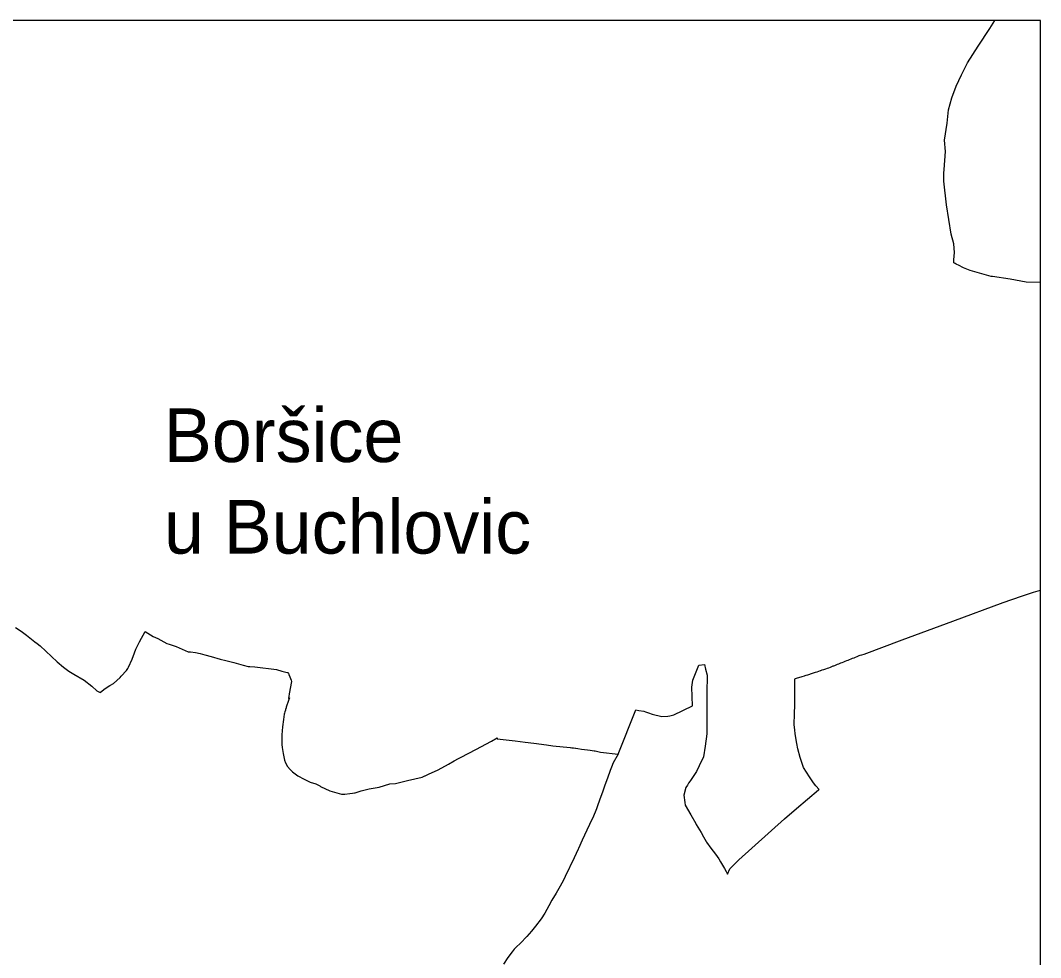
# Model space of a CAD drawing. Extents: x -552716 to -540720, y -1192685 to -1177912.
# Drawn here: x -546493 to -543896, y -1183546 to -1181162 of the extents above; entities that cross this region are included whole.
import ezdxf

# ---------------------------------------------------------------- set-up
doc = ezdxf.new("R2010")
doc.units = 0
doc.layers.add('Vrstva 1', color=7, linetype='Continuous')
doc.layers.add('Vrstva 60', color=7, linetype='Continuous')

msp = doc.modelspace()

# ---------------------------------------------------------------- linework, layer by layer
at = {"layer": 'Vrstva 1'}
for p, q in [((-546504.7, -1182705.9), (-546490.6, -1182715.5)), ((-546490.6, -1182715.5), (-546477.2, -1182725.3)), ((-546477.2, -1182725.3), (-546455.6, -1182742.2)), ((-546189.2, -1182742.6), (-546174.9, -1182716.2)), ((-546174.9, -1182716.2), (-546154.4, -1182729.1)), ((-546154.4, -1182729.1), (-546143, -1182734.3)), ((-546143, -1182734.3), (-546120.1, -1182746.8)), ((-546455.6, -1182742.2), (-546449.7, -1182746.6)), ((-546449.7, -1182746.6), (-546442.5, -1182752.4)), ((-546442.5, -1182752.4), (-546413.2, -1182780)), ((-546202.6, -1182770.3), (-546198.6, -1182761.4)), ((-546198.6, -1182761.4), (-546189.2, -1182742.6)), ((-546120.1, -1182746.8), (-546114.2, -1182748.4)), ((-546114.2, -1182748.4), (-546096.2, -1182754)), ((-546096.2, -1182754), (-546065.9, -1182767.7)), ((-546413.2, -1182780), (-546399.4, -1182793.2)), ((-546217.8, -1182807), (-546208.3, -1182786.7)), ((-546208.3, -1182786.7), (-546202.6, -1182770.3)), ((-546065.9, -1182767.7), (-546059.3, -1182767.9)), ((-546059.3, -1182767.9), (-546046.7, -1182769.2)), ((-546046.7, -1182769.2), (-546035.1, -1182772.4)), ((-546035.1, -1182772.4), (-546023.6, -1182775.5)), ((-546023.6, -1182775.5), (-546007.3, -1182779.9)), ((-546007.3, -1182779.9), (-545983.8, -1182786.2)), ((-545983.8, -1182786.2), (-545969.8, -1182789.8)), ((-546399.4, -1182793.2), (-546382.8, -1182806.7)), ((-546382.8, -1182806.7), (-546369.4, -1182816.8)), ((-546222.5, -1182815.2), (-546219.5, -1182810.1)), ((-546219.5, -1182810.1), (-546217.8, -1182807)), ((-545969.8, -1182789.8), (-545949.7, -1182795.1)), ((-545949.7, -1182795.1), (-545925.6, -1182801.7)), ((-545925.6, -1182801.7), (-545912.9, -1182805.1)), ((-545912.9, -1182805.1), (-545909, -1182805.6)), ((-545909, -1182805.6), (-545896.2, -1182806.4)), ((-545896.2, -1182806.4), (-545840.9, -1182813)), ((-545840.9, -1182813), (-545827.6, -1182816.9)), ((-546369.4, -1182816.8), (-546356.5, -1182825.1)), ((-546356.5, -1182825.1), (-546330.2, -1182840.2)), ((-546330.2, -1182840.2), (-546310.5, -1182854.9)), ((-546256, -1182848.8), (-546238.6, -1182832.8)), ((-546238.6, -1182832.8), (-546236.2, -1182830.2)), ((-546236.2, -1182830.2), (-546222.5, -1182815.2)), ((-545827.6, -1182816.9), (-545813.9, -1182820.1)), ((-545813.9, -1182820.1), (-545811.1, -1182820.6)), ((-545811.1, -1182820.6), (-545810.5, -1182822.2)), ((-545810.5, -1182822.2), (-545809.2, -1182825.5)), ((-545809.2, -1182825.5), (-545806.8, -1182831.4)), ((-545806.8, -1182831.4), (-545803.7, -1182839.6)), ((-545803.7, -1182839.6), (-545802.4, -1182843)), ((-546310.5, -1182854.9), (-546298.3, -1182866.7)), ((-546288.5, -1182870.7), (-546276.8, -1182861)), ((-546276.8, -1182861), (-546264.7, -1182853.9)), ((-546264.7, -1182853.9), (-546256, -1182848.8)), ((-545802.4, -1182843), (-545808.5, -1182874.6)), ((-546298.3, -1182866.7), (-546289.7, -1182871.7)), ((-546289.7, -1182871.7), (-546288.5, -1182870.7)), ((-545810.3, -1182891.7), (-545815.8, -1182908.9)), ((-545810.4, -1182886.7), (-545807.4, -1182885.2)), ((-545810.2, -1182885.4), (-545810.4, -1182886.7)), ((-545807.4, -1182885.2), (-545810.3, -1182891.7)), ((-545809.8, -1182881.8), (-545810.2, -1182885.4)), ((-545809.7, -1182881.1), (-545809.8, -1182881.8)), ((-545808.5, -1182874.8), (-545809.7, -1182881.1)), ((-545808.5, -1182874.6), (-545808.5, -1182874.8)), ((-545818.1, -1182916.1), (-545819.7, -1182920.9)), ((-545818, -1182915.6), (-545818.1, -1182916.1)), ((-545817.9, -1182915.3), (-545818, -1182915.6)), ((-545817.6, -1182914.4), (-545817.9, -1182915.3)), ((-545816.4, -1182910.6), (-545817.6, -1182914.4)), ((-545815.8, -1182908.9), (-545816.4, -1182910.6)), ((-545823.1, -1182939.7), (-545825.3, -1182958.4)), ((-545821.4, -1182926.8), (-545823.1, -1182939.7)), ((-545820.7, -1182924.1), (-545821.4, -1182926.8)), ((-545819.7, -1182920.9), (-545820.7, -1182924.1)), ((-545825.3, -1182958.4), (-545827.3, -1182979)), ((-545827.3, -1182979), (-545827.4, -1183003.3)), ((-545333.5, -1183016.5), (-545293.9, -1182995.4)), ((-545293.9, -1182995.4), (-545279.6, -1182986.4)), ((-545279.6, -1182986.4), (-545278.8, -1182988.8)), ((-545278.8, -1182988.8), (-545233.3, -1182994.7)), ((-545233.3, -1182994.7), (-545207.8, -1182997.7)), ((-545827.4, -1183003.3), (-545826.2, -1183010.9)), ((-545826.2, -1183010.9), (-545823.9, -1183026.7)), ((-545370.5, -1183035.6), (-545333.5, -1183016.5)), ((-545207.8, -1182997.7), (-545185.9, -1183000.4)), ((-545185.9, -1183000.4), (-545153.4, -1183004.7)), ((-545153.4, -1183004.7), (-545137.4, -1183006.8)), ((-545137.4, -1183006.8), (-545093.3, -1183011.2)), ((-545093.3, -1183011.2), (-545092.8, -1183011.3)), ((-545092.8, -1183011.3), (-545089.5, -1183011.7)), ((-545089.5, -1183011.7), (-545084.8, -1183012.4)), ((-545084.8, -1183012.4), (-545080, -1183013)), ((-545080, -1183013), (-545079.8, -1183013)), ((-545079.8, -1183013), (-545079, -1183013.1)), ((-545079, -1183013.1), (-545073.6, -1183013.9)), ((-545073.6, -1183013.9), (-545064.4, -1183015.2)), ((-545064.4, -1183015.2), (-545056.8, -1183016.2)), ((-545056.8, -1183016.2), (-545049, -1183017.4)), ((-545049, -1183017.4), (-545042.8, -1183018.2)), ((-545042.8, -1183018.2), (-545032.4, -1183019.7)), ((-545032.4, -1183019.7), (-545029.5, -1183020.1)), ((-545029.5, -1183020.1), (-545015.8, -1183023)), ((-545823.9, -1183026.7), (-545820.4, -1183043.7)), ((-545820.4, -1183043.7), (-545817.6, -1183050.4)), ((-545402.9, -1183054), (-545388.8, -1183045.3)), ((-545388.8, -1183045.3), (-545377.6, -1183039.2)), ((-545377.6, -1183039.2), (-545370.5, -1183035.6)), ((-545015.8, -1183023), (-544971.2, -1183027.9)), ((-544971.2, -1183027.9), (-544983.9, -1183050.4)), ((-545817.6, -1183050.4), (-545812.9, -1183059.4)), ((-545812.9, -1183059.4), (-545805.9, -1183067.4)), ((-545805.9, -1183067.4), (-545805.8, -1183067.5)), ((-545805.8, -1183067.5), (-545800.4, -1183073.5)), ((-545800.4, -1183073.5), (-545786.6, -1183083.1)), ((-545453.7, -1183079), (-545429.5, -1183067.7)), ((-545429.5, -1183067.7), (-545402.9, -1183054)), ((-544991.2, -1183069.6), (-544998.3, -1183088.9)), ((-544988.2, -1183061.7), (-544991.2, -1183069.6)), ((-544983.9, -1183050.4), (-544988.2, -1183061.7)), ((-545786.6, -1183083.1), (-545770.7, -1183092)), ((-545770.7, -1183092), (-545755.1, -1183099.5)), ((-545755.1, -1183099.5), (-545740.6, -1183103.7)), ((-545538.1, -1183102.6), (-545507.2, -1183094.9)), ((-545507.2, -1183094.9), (-545470.1, -1183086.6)), ((-545470.1, -1183086.6), (-545463.4, -1183083.4)), ((-545463.4, -1183083.4), (-545462.8, -1183083.2)), ((-545462.8, -1183083.2), (-545454.1, -1183079.1)), ((-545454.1, -1183079.1), (-545453.7, -1183079)), ((-544998.3, -1183088.9), (-545004.9, -1183107.1)), ((-545740.6, -1183103.7), (-545732.3, -1183108.3)), ((-545732.3, -1183108.3), (-545730.6, -1183108.7)), ((-545730.6, -1183108.7), (-545728.6, -1183110.1)), ((-545728.6, -1183110.1), (-545705.2, -1183121.6)), ((-545705.2, -1183121.6), (-545675.1, -1183129.8)), ((-545640.6, -1183126.8), (-545625.6, -1183121.9)), ((-545625.6, -1183121.9), (-545604.6, -1183116.8)), ((-545604.6, -1183116.8), (-545579.8, -1183112.1)), ((-545579.8, -1183112.1), (-545552.5, -1183103.4)), ((-545552.5, -1183103.4), (-545538.1, -1183102.6)), ((-545011.2, -1183124.6), (-545017.7, -1183142.5)), ((-545004.9, -1183107.1), (-545011.2, -1183124.6)), ((-545675.1, -1183129.8), (-545666.6, -1183130.1)), ((-545666.6, -1183130.1), (-545654, -1183128.4)), ((-545654, -1183128.4), (-545647.5, -1183127.6)), ((-545647.5, -1183127.6), (-545642.4, -1183127)), ((-545642.4, -1183127), (-545641.5, -1183126.9)), ((-545641.5, -1183126.9), (-545640.6, -1183126.8)), ((-545017.7, -1183142.5), (-545024.8, -1183162.2)), ((-545027.9, -1183171.3), (-545033.9, -1183186.2)), ((-545026.5, -1183167.2), (-545027.9, -1183171.3)), ((-545025.5, -1183164.4), (-545026.5, -1183167.2)), ((-545024.8, -1183162.2), (-545025.5, -1183164.4)), ((-545033.9, -1183186.2), (-545043.9, -1183207.4)), ((-545050.6, -1183221.6), (-545062.7, -1183246.6)), ((-545043.9, -1183207.4), (-545050.6, -1183221.6)), ((-545062.7, -1183246.6), (-545072.4, -1183268.6)), ((-545073, -1183269.7), (-545083.1, -1183292.1)), ((-545072.4, -1183268.6), (-545073, -1183269.7)), ((-545083.1, -1183292.2), (-545106, -1183339.5)), ((-545083.1, -1183292.1), (-545083.1, -1183292.2)), ((-545110.4, -1183348.7), (-545119.1, -1183364.1)), ((-545106, -1183339.5), (-545110.4, -1183348.7)), ((-545129, -1183382.2), (-545139.8, -1183400)), ((-545119.1, -1183364.1), (-545129, -1183382.2)), ((-545139.8, -1183400), (-545148.1, -1183414)), ((-545158.1, -1183433), (-545167.1, -1183447.1)), ((-545148.1, -1183414), (-545158.1, -1183433)), ((-545167.1, -1183447.1), (-545181.6, -1183465.7)), ((-545192.2, -1183478.2), (-545203.9, -1183492.3)), ((-545181.6, -1183465.7), (-545192.2, -1183478.2)), ((-545220.1, -1183509.2), (-545230.7, -1183519.3)), ((-545203.9, -1183492.3), (-545220.1, -1183509.2)), ((-545241.2, -1183530.7), (-545251.8, -1183545.4)), ((-545236.2, -1183524.6), (-545241.2, -1183530.7)), ((-545230.7, -1183519.3), (-545236.2, -1183524.6)), ((-545251.8, -1183545.4), (-545263.3, -1183562.3))]:
    msp.add_line(p, q, dxfattribs=at)
for points in [[(-544097, -1181300), (-544082.2, -1181269.4), (-544055.3, -1181227.2), (-544025.5, -1181182.3), (-544012.6, -1181161.6)], [(-543896.1, -1181828.2), (-543933.1, -1181827.3), (-543973.6, -1181819.7), (-544018.6, -1181813.2), (-544021.6, -1181812.7), (-544075.2, -1181797.5), (-544092.6, -1181791.4), (-544105.4, -1181784.6), (-544109, -1181782.5), (-544110.9, -1181781.3), (-544113.4, -1181779.8), (-544115.1, -1181778.8), (-544117.1, -1181778), (-544116.9, -1181774.8), (-544116.7, -1181771.1), (-544115.4, -1181752), (-544117.2, -1181730.3), (-544123.7, -1181705.2), (-544135.3, -1181630.4), (-544142.6, -1181570.2), (-544142.4, -1181564), (-544142, -1181550.2), (-544141.8, -1181540.7), (-544137.9, -1181495.1), (-544140.9, -1181466.6), (-544133.8, -1181423), (-544130.2, -1181389.4), (-544122.2, -1181358.4), (-544111.1, -1181328.5), (-544097, -1181300)], [(-544483.8, -1182824.5), (-544482, -1182823.9), (-544478.9, -1182822.9), (-544474.4, -1182821.4), (-544469, -1182819.7), (-544465, -1182818.4), (-544460.9, -1182817), (-544456.4, -1182815.6), (-544455.8, -1182815.4), (-544451.8, -1182814), (-544447.4, -1182812.6), (-544442.9, -1182811), (-544438.8, -1182809.7), (-544438.4, -1182809.5), (-544435.3, -1182808.3), (-544431.2, -1182806.7), (-544427.1, -1182805.1), (-544423.8, -1182803.8), (-544422.5, -1182803.3), (-544419.9, -1182802.3), (-544416.4, -1182800.9), (-544413, -1182799.5), (-544409.2, -1182798), (-544404.9, -1182796.3), (-544401.2, -1182794.8), (-544397.3, -1182793.3), (-544393.5, -1182791.8), (-544389.6, -1182790.2), (-544385.8, -1182788.7), (-544382.2, -1182787.2), (-544378.4, -1182785.7), (-544374.4, -1182784.1), (-544370.9, -1182782.8), (-544366.9, -1182781.2), (-544363.2, -1182779.7), (-544359.9, -1182778.4), (-544358, -1182777.6), (-544355.5, -1182776.6), (-544350.7, -1182775.2), (-544344.8, -1182773.5), (-544248.1, -1182737.1), (-544119.8, -1182689.8), (-543991.4, -1182642.5), (-543945, -1182626.7), (-543914.3, -1182616.4), (-543896.1, -1182611.1)], [(-544971.2, -1183027.9), (-544926.3, -1182915.7), (-544918.6, -1182916.8), (-544905.8, -1182918.9), (-544901.4, -1182920.4), (-544894.4, -1182922.7), (-544884.4, -1182926.1), (-544860.2, -1182932.7), (-544845.2, -1182931.4), (-544840, -1182930.3), (-544829.3, -1182928.4), (-544781.7, -1182905.4), (-544783.8, -1182857.5), (-544781.3, -1182839.9), (-544766.2, -1182801.9), (-544751.5, -1182800.5), (-544748.7, -1182812.3), (-544745, -1182827.4), (-544745, -1182839.3), (-544745.3, -1182861.5), (-544745.4, -1182883), (-544745.4, -1182928.1), (-544745.2, -1182954), (-544745.4, -1182961.6), (-544745.9, -1182976.1), (-544749.8, -1183008), (-544754, -1183035.4), (-544764.7, -1183057.9), (-544771.6, -1183072.3), (-544785.3, -1183092.5), (-544791.3, -1183101.4), (-544791.8, -1183102.3), (-544795, -1183107), (-544799, -1183112.9), (-544804.2, -1183132.2), (-544801.6, -1183150.9), (-544800.7, -1183157.8), (-544786.5, -1183182.3), (-544773.7, -1183204.5), (-544772.3, -1183206.8), (-544759.9, -1183227.9), (-544754.3, -1183238.1), (-544747.4, -1183250.8), (-544746.2, -1183252.3), (-544735.1, -1183267.3), (-544723.4, -1183282.8), (-544715.3, -1183294.7), (-544710.9, -1183301.9), (-544700.9, -1183319.4), (-544696.7, -1183326.7), (-544693.1, -1183333.2), (-544687.2, -1183319.5), (-544664.2, -1183297.1), (-544548.1, -1183192.4), (-544517.4, -1183166.2), (-544461.1, -1183119.2), (-544460, -1183118.3), (-544467.9, -1183108.6), (-544473.8, -1183100.9), (-544484, -1183086.2), (-544499.7, -1183061.8), (-544507.8, -1183037.1), (-544514, -1183014.9), (-544516.7, -1183000.7), (-544520.9, -1182976.9), (-544522, -1182966.6), (-544523.2, -1182953.5), (-544522.7, -1182924.8), (-544522, -1182903.5), (-544521.7, -1182884), (-544521.7, -1182866), (-544521.9, -1182836.7), (-544520.4, -1182836.2), (-544519.7, -1182836), (-544517.1, -1182835.2), (-544503.3, -1182830.9), (-544497.3, -1182829.1), (-544495.6, -1182828.5), (-544492.8, -1182827.6), (-544488.1, -1182826), (-544483.8, -1182824.5)]]:
    msp.add_lwpolyline(points, dxfattribs=at)
at = {"layer": 'Vrstva 60'}
msp.add_lwpolyline([(-543896.1, -1181161.6), (-549696, -1181161.6), (-549696, -1188366.4), (-543896.1, -1188366.4)], close=True, dxfattribs=at)

# ---------------------------------------------------------------- texts
at = {"layer": 'Vrstva 1'}
for s, height, p in [('Boršice', 136.69, (-546127.4, -1182285.1)), ('u Buchlovic', 136.688, (-546127.4, -1182518))]:
    msp.add_text(s, height=height, dxfattribs=at).set_placement(p)

doc.saveas('drawing.dxf')
